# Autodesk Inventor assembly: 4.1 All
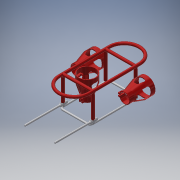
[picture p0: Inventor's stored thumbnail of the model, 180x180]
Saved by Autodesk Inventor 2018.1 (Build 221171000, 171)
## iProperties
Created: 2018-06
Part Number: 4.1 All
Document SubType Name: Assembly
Designer: Ryan
Author: Ryan
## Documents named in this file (4)
- C:\Users\Ryan\Desktop\Seaperch 2018\ROV V4.2\4.1\4.1 All.iam
- C:\Users\Ryan\Desktop\Seaperch 2018\ROV V4.2\4.1\4.1 Top.iam
- C:\Users\Ryan\Desktop\Seaperch 2018\ROV V4.2\Rov v4.2 Base.ipt
- C:\Users\Ryan\Desktop\Seaperch 2018\ROV V4.2\Part1.ipt
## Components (4 placed, 3 different names)
1. 4.1 Top:1 [sub-assembly] — Mate:1, Mate:2, Mate:3, Mate:6
2. Rov v4.2 Base:1 — Mate:1, Mate:2, Mate:3, Mate:4, Mate:5, Flush:2
3. Part1:1 — Mate:5, Flush:1
4. Part1:2 — Mate:4, Flush:1, Flush:2, Mate:6
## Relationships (8: Mate 6, Flush 2)
- Mate:1: 4.1 Top:1 ↔ Rov v4.2 Base:1
- Mate:2: 4.1 Top:1 ↔ Rov v4.2 Base:1
- Mate:3: 4.1 Top:1 ↔ Rov v4.2 Base:1
- Mate:4: Rov v4.2 Base:1 ↔ Part1:2
- Mate:5: Rov v4.2 Base:1 ↔ Part1:1
- Flush:1: Part1:1 ↔ Part1:2
- Flush:2: Rov v4.2 Base:1 ↔ Part1:2
- Mate:6: 4.1 Top:1 ↔ Part1:2
